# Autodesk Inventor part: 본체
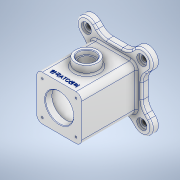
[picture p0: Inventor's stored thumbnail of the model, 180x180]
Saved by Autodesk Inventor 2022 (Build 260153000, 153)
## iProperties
Created: 2022-05
Part Number: 본체
Material: 알루미늄 6061
Document SubType Name: Modeling
Designer: Admin
Density: 2.7 g/cm^3
Appearance: 알루미늄 - 평지
Mass: 1072.96 g
Surface Area: 876.126 cm^2
Volume: 397.392 cm^3
Author: Admin
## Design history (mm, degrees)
sketch "스케치1"
  geometry: L1 (-56, 0)-(56, 0) reference; L2 (0, -56)-(0, 56) reference; L3 (-40, 40)-(40, 40); L4 (40, 40)-(40, -40); L5 (40, -40)-(-40, -40); L6 (-40, -40)-(-40, 40); L7 (-40, 40)-(40, -40); L8 (40, 40)-(-40, -40); 1 further point
  constraints: 12 end point, 2 midpoint, 2 parallel, 1 horizontal, 1 perpendicular
  dimensions: "d0" = 80 distance of L3.start L3.end; "d1" = 80 distance of L3.end L4.end
extrude "돌출1" new body sketch "스케치1" stored distance "d2" = 110; taper "d3" = 0 deg
fillet "모깎기1" dims "d4" = 10
sketch "스케치2"
  geometry: L1 (-22.753, 22.753)-(-9.988, 9.988); L2 (30, 40)-(-30, 40) reference; L3 (40, -30)-(40, 30) reference; L4 (30, 40)-(-30, 40) reference; L5 (-40, 30)-(-40, -30) reference; L6 (-30, -40)-(30, -40) reference; L7 (0, 0)-(-18.736, 18.736); L8 (0, -62.867)-(0, 82.702) reference; L9 (-49, 49)-(49, 49); L10 (49, 49)-(49, -49); L11 (49, -49)-(-49, -49); L12 (-49, -49)-(-49, 49); L13 (-49, 49)-(49, -49); L14 (49, 49)-(-49, -49); L15 (-49, 49)-(-40, 40); L16 (-61.728, 36.272)-(-52.728, 27.272); L17 (-27.272, 52.728)-(-36.272, 61.728); L18 (27.272, 52.728)-(36.272, 61.728); L19 (61.728, 36.272)-(52.728, 27.272); L20 (104.238, 0)-(-104.238, 0) reference; L21 (-61.728, -36.272)-(-52.728, -27.272); L22 (-27.272, -52.728)-(-36.272, -61.728); L23 (27.272, -52.728)-(36.272, -61.728); L24 (61.728, -36.272)-(52.728, -27.272); A1 r 10 centre (30, -30) between (30, -40) and (40, -30) reference; A2 r 10 centre (30, 30) between (40, 30) and (30, 40) reference; A3 r 10 centre (-30, 30) between (-30, 40) and (-40, 30) reference; A4 r 10 centre (-30, -30) between (-40, -30) and (-30, -40) reference; A5 r 18 centre (-49, 49) between (-36.272, 61.728) and (-61.728, 36.272); A6 r 18 centre (-40, 40) between (-52.728, 27.272) and (-27.272, 52.728); A7 r 18 centre (49, 49) between (61.728, 36.272) and (36.272, 61.728); A8 r 18 centre (40, 40) between (27.272, 52.728) and (52.728, 27.272); A9 r 18 centre (-49, -49) between (-61.728, -36.272) and (-36.272, -61.728); A10 r 18 centre (-40, -40) between (-27.272, -52.728) and (-52.728, -27.272); A11 r 18 centre (49, -49) between (36.272, -61.728) and (61.728, -36.272); A12 r 18 centre (40, -40) between (52.728, -27.272) and (27.272, -52.728); 9 further points
  constraints: 38 end point, 16 point on circle, 15 symmetric about line, 8 centre point, 4 tangent, 3 midpoint, 3 parallel, 3 point on line, 1 collinear, 1 horizontal, 1 perpendicular, 6 other
  dimensions: "d6" = 98 distance of L9.start L9.end; "d7" = 98 distance of L9.end L10.end; "d8" = 36 distance between parallel lines of L17 L16
extrude "돌출2" join sketch "스케치2" distance "d9" = 12; taper "d10" = 0 deg
sketch "스케치4" dims "d12" = 140
  geometry: L1 (-49.497, 49.497)-(0, 0); L2 (0, -104.342)-(0, 104.858) reference; L3 (-104.858, 0)-(104.342, 0) reference; L4 (49.497, 49.497)-(0, 0); L5 (-49.497, -49.497)-(0, 0); L6 (49.497, -49.497)-(0, 0); A1 r 18.014 centre (-49.497, 49.497) between (-36.272, 61.728) and (-61.728, 36.272); A2 r 18 centre (49, 49) between (61.728, 36.272) and (36.272, 61.728) reference; A3 r 18 centre (49, -49) between (36.272, -61.728) and (61.728, -36.272) reference; A4 r 18 centre (-49, -49) between (-61.728, -36.272) and (-36.272, -61.728) reference; 5 further points
  constraints: 8 end point, 5 coincident, 3 symmetric about line, 2 point on circle, 1 centre point, 3 other
hole "구멍1" sketch "스케치4" at (-49.497, 49.497), (49.497, 49.497), (49.497, -49.497), (-49.497, -49.497) diameter "d13" = 10; stored, may be unused: countersink angle "d17" = 90 deg, drill point angle "d19" = 118 deg; dims "d14" = 6, "d15" = 18, "d16" = 4, "d18" = 8
sketch "스케치5"
  geometry: L1 (-30, 30)-(30, 30); L2 (30, 30)-(30, -30); L3 (30, -30)-(-30, -30); L4 (-30, -30)-(-30, 30); L5 (-30, 30)-(30, -30); L6 (30, 30)-(-30, -30); A1 r 10 centre (-30, 30) between (-30, 40) and (-40, 30) reference; 5 further points
  constraints: 12 end point, 4 coincident, 2 midpoint, 2 parallel, 1 horizontal, 1 perpendicular
  dimensions: "d20" = 60 distance of L2.end L3.end; "d21" = 60 distance of L1.end L2.end
hole "구멍2" sketch "스케치5" at (-30, 30), (30, 30), (30, -30), (-30, -30) diameter "d22" = 3.242; stored, may be unused: countersink angle "d26" = 90 deg, drill point angle "d28" = 118 deg; dims "d23" = 8, "d24" = 18, "d25" = 4, "d27" = 10
node "작업 평면1"
sketch "스케치6"
  geometry: L1 (67, -43)-(36.272, -43) reference; C1 r 20 at (0, 6); 2 further points
  constraints: 1 centre point
  dimensions: "d31" = 40 diameter of C1; "d32" = 49 distance from line of L1 C1.centre
extrude "돌출3" join sketch "스케치6" stored distance "d33" = 12; taper "d34" = 0 deg
sketch "스케치7"
  geometry: C1 r 20 at (0, 0) reference; C2 r 15 at (0, 0)
  constraints: 1 centre point, 1 coincident
  dimensions: "d35" = 30 diameter of C2
extrude "돌출4" cut sketch "스케치7" distance "d36" = 8; taper "d37" = 0 deg
sketch "스케치9"
  geometry: L1 (0, -77)-(0, 77) reference; L2 (30, 55)-(-30, 55) reference; L3 (0, 55)-(25, 55); L4 (25, 55)-(25, 43); L5 (25, 43)-(0, 43); L6 (0, 43)-(0, 55); L7 (0, 43)-(35, 43); L8 (35, 43)-(35, -43); L9 (35, -43)-(0, -43); L10 (0, -43)-(0, 43); L11 (-24.412, -55)-(24.412, -55) reference; L12 (0, -43)-(25, -43); L13 (25, -43)-(25, -55); L14 (25, -55)-(0, -55); L15 (0, -55)-(0, -43); 6 further points
  constraints: 24 end point, 6 parallel, 3 horizontal, 3 perpendicular, 1 midpoint, 1 point on line
  dimensions: "d38" = 12 distance between parallel lines of L5 L2; "d39" = 86 distance between parallel lines of L12 L7; "d40" = 50 diameter of L4 L1; "d41" = 50 diameter of L13 L1; "d42" = 70 diameter of L8 L1
revolve "회전1" sketch "스케치9" stored, may be unused: angle "d43" = 90 deg
sketch "스케치10"
  geometry: C1 r 15 at (0, 0) reference; C2 r 12.5 at (0, 0); 1 further point
  constraints: 1 centre point, 1 coincident
  dimensions: "d44" = 25 diameter of C2
extrude "돌출5" cut sketch "스케치10" stored distance "d45" = 8; taper "d46" = 0 deg
sketch "스케치11"
  geometry: L1 (-30, 30)-(30, 30); L2 (30, 30)-(30, -30); L3 (30, -30)-(-30, -30); L4 (-30, -30)-(-30, 30); L5 (-30, 30)-(30, -30); L6 (30, 30)-(-30, -30); C1 r 1.621 at (-30, 30) reference; C2 r 1.621 at (30, -30) reference; 5 further points
  constraints: 12 end point, 4 coincident, 2 midpoint, 2 parallel, 1 horizontal, 1 perpendicular
  dimensions: "d47" = 60 distance of L2.end L3.end; "d48" = 60 distance of L1.end L2.end
hole "구멍3" sketch "스케치11" at (-30, 30), (30, 30), (30, -30), (-30, -30) diameter "d49" = 3.242; stored, may be unused: countersink angle "d53" = 90 deg, drill point angle "d55" = 118 deg; dims "d50" = 8, "d51" = 4, "d52" = 2, "d54" = 10
fillet "모깎기2" dims "d56" = 25
fillet "모깎기3" dims "d57" = 3
fillet "모깎기4" dims "d58" = 3
chamfer "모따기1" distance "d59" = 1; stored, may be unused: second distance "d60" = 2, angle "d61" = 45 deg
fillet "모깎기5" dims "d62" = 3
sketch "스케치12"
  geometry: L1 (60, 0)-(0, 0) reference; L2 (30, 132)-(30, -22) reference; 2 further points
  constraints: 1 point on line, 1 other
  dimensions: "d63" = 10 distance from line of L1 point (30, 10)
feature "엠보싱1" sketch "스케치12" dims "d0" = 80, "d1" = 80, "d4" = 10, "d64" = 0.5, "d65" = 0
node "솔리드1"
node "투영된 루프1"
node "투영된 루프2"
feature "A9D066F2-1C7D-4E18-AEED-F7BC21143FA4" dims "d13" = 10, "d14" = 6, "d15" = 18, "d16" = 4, "d17" = 90 deg, "d18" = 8, "d19" = 118 deg
other parameters: "d29" = 55
